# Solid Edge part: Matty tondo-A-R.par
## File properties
Title: Matty tondo/A/R
Author: DESYS
Template: Normal.par
Last saved by: s.pallini
Revision: 16
Application: Solid Edge
Tipo di contenuto documento: 0
Precisione: 0,990
Document Number: 8055/A/R
Revision: 0
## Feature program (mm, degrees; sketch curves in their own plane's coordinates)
sketch for "unnamed RevolvedProtrusion 1" plane through (0, 0, 0) normal (0, -1, 0) x-axis (1, 0, 0)
  line (-103.413, -287.9981) -> (-129.488, -287.9981)
  arc centre (-129.488, -279.9013) radius 8.0968 from (-136.7557, -283.4704) to (-129.488, -287.9981) ccw
  arc centre (491.5651, 25.0957) radius 700 from (-186.9381, -147.0479) to (-136.7557, -283.4704) ccw
  arc centre (-196.631, -149.5071) radius 10 from (-186.9381, -147.0479) to (-196.631, -139.5071) ccw
  line (-207.631, -139.5071) -> (-196.631, -139.5071)
  arc centre (469.5217, 37.8744) radius 700 from (-229.7181, 5.2599) to (-207.631, -139.5071) ccw
  arc centre (-224.7235, 5.4929) radius 5 from (-223.4856, 10.3372) to (-229.7181, 5.2599) ccw
  line (-223.4856, 10.3372) -> (-198.051, 3.8377)
  arc centre (-199.2889, -1.0066) radius 5 from (-194.3913, 0) to (-198.051, 3.8377) ccw
  arc centre (50.4896, 50.3322) radius 250 from (-194.3913, 0) to (-25, -187.9981) ccw
  line (0, -187.9981) -> (-25, -187.9981)
  line (-30, -227.9981) -> (0, -227.9981)
  arc centre (-30, -222.9981) radius 5 from (-35, -222.9981) to (-30, -227.9981) ccw
  line (-35, -211.5908) -> (-35, -222.9981)
  arc centre (-40, -211.5908) radius 5 from (-35, -211.5908) to (-38.2474, -206.908) ccw
  arc centre (-20.7216, -160.0802) radius 50 from (-55.0901, -196.3956) to (-38.2474, -206.908) ccw
  arc centre (-58.5269, -200.0271) radius 5 from (-55.0901, -196.3956) to (-63.1521, -198.1276) ccw
  line (-98.7879, -284.8976) -> (-63.1521, -198.1276)
  arc centre (-103.413, -282.9981) radius 5 from (-103.413, -287.9981) to (-98.7879, -284.8976) ccw
  dimension (linear) = 223.4856
revolve "unnamed RevolvedProtrusion 1" add full turn 360 deg about sketch line (0, -187.9981) -> (0, -227.9981)
sketch for "unnamed RevolvedCutout 1" plane through (0, 0, 0) normal (1, 0, 0) x-axis (0, 1, 0)
  line (-227.9568, -21.4867) -> (-200.6198, -21.4867)
  arc centre (93.1464, 39.3526) radius 300 from (-200.6198, -21.4867) to (-69.2229, -212.9095) ccw
revolve "unnamed RevolvedCutout 1" cut finite
fillet "Rotondo_1" radius 5
sketch for "Foro_1" plane through (0, 0, -187.9981) normal (0, 0, 1) x-axis (0, -1, 0)
  hole centre (0, 0) bore radius 25
hole "Foro_1" diameter 50 through
fillet "Rotondo_4" radius 10
fillet "Rotondo_5" radius 5
sketch for "Foro_3" plane through (0, 9.4953, -287.9981) normal (0, 0, -1) x-axis (-0.34202, 0.939693, 0)
  hole centre (31.4357, -114.1313) bore radius 7.5
hole "Foro_3" diameter 15 finite
sketch for "unnamed Hole 1" plane through (0, 9.4953, -287.9981) normal (0, 0, -1) x-axis (-0.34202, 0.939693, 0)
  hole centre (-49.281, 107.6361) bore radius 7.5
hole "unnamed Hole 1" finite
sketch for "unnamed Hole 2" plane through (0, 9.4953, -287.9981) normal (0, 0, -1) x-axis (-0.34202, 0.939693, 0)
  hole centre (101.9611, 37.1108) bore radius 7.5
hole "unnamed Hole 2" finite
fillet "Rotondo_7" radius 5
sketch for "unnamed Protrusion 1" plane through (0, 0, 0) normal (0, 0, 1) x-axis (1, 0, 0)
extrude "unnamed Protrusion 1" add through along -normal
sketch for "Foro_7" plane through (0, 0, 0) normal (0, -1, 0) x-axis (1, 0, 0)
hole "Foro_7" diameter 20 finite
sketch for "ScavoEstrusione_2" plane through (0, 0, 0) normal (1, 0, 0) x-axis (0, 1, 0)
extrude "ScavoEstrusione_2" cut finite 133 symmetric
draft "Spoglia_2"  Angles1 = 6.2 deg
draft "Spoglia_3"  Angles1 = 6.2 deg
fillet "Rotondo_8" radius 10
sketch for "ExtrudedProtrusion_2" plane through (0, 0, 0) normal (1, 0, 0) x-axis (0, 1, 0)
  line (-26.903, -223.5492) -> (-75.9297, -220.2121)
  line (-26.903, -198.1276) -> (-26.903, -223.5492)
  line (-50.898, -188.8164) -> (-26.903, -198.1276)
  line (-101.6779, -155.4366) -> (-50.898, -188.8164)
  line (-113.3964, -131.6446) -> (-101.6779, -155.4366)
  line (-113.3964, -12.3296) -> (-113.3964, -131.6446)
  line (-145.3557, -12.3296) -> (-113.3964, -12.3296)
  line (-145.3557, -12.3296) -> (-145.3557, -125.3143)
  arc centre (-73.461, -125.3143) radius 71.8947 from (-125.5893, -174.8269) to (-145.3557, -125.3143) cw
  line (-125.5893, -174.8269) -> (-85.5645, -216.9662)
  arc centre (-74.5715, -200.2583) radius 20 from (-85.5645, -216.9662) to (-75.9297, -220.2121) ccw
extrude "ExtrudedProtrusion_2" add finite 30 symmetric
fillet "Rotondo_9" radius 10
fillet "Rotondo_10" radius 5
fillet "Rotondo_11" radius 5
fillet "Rotondo_12" radius 5
sketch for "Foro_8" plane through (0, -149.5574, 0) normal (0, 0, 1) x-axis (1, 0, 0)
hole "Foro_8" diameter 35 through
fillet "Rotondo_13" radius 5
fillet "Rotondo_14" radius 10
fillet "Rotondo_15" radius 20
fillet "Rotondo_16" radius 5
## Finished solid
Body 1: solid body, 136 faces, 301 edges, 166 vertices.
  Faces by surface: blend 50, cylinder 34, torus 30, plane 16, sphere 4, cone 2
  Edges by curve: circle 130, intersection 102, line 57, ellipse 12
Bounding box of the edges (mm; curved faces can reach further): 459.436 x 459.436 x 298.335, from (-229.7181, -229.7181, -287.9981) to (229.7181, 229.7181, 10.3372).
Cylindrical faces by radius (mm): R5 x17, R10 x6, R17.5 x1, R20 x1, R25 x1, R35 x1, R56.278 x2, R60.9772 x2, R71.8947 x1, R251.0525 x2
Conical faces (half-angle, radius in mm at the cone's reference point): 22.3276 deg R63.1521 x1, 75.6654 deg R223.4856 x1
Toroidal faces (ring radius, tube radius in mm): R-491.5651 r700 x1, R-469.5217 r700 x1, R-50.4896 r250 x1, R10 r5 x2, R15 r5 x2, R20.7216 r50 x1, R22.5 r5 x1, R30 r5 x1, R35 r10 x1, R40 r5 x1, R51.278 r5 x2, R58.5269 r5 x1, R65.9772 r5 x2, R66.8947 r5 x2, R103.413 r5 x1, R129.488 r8.0968 x1, R185.7346 r20 x2, R196.631 r10 x1, R199.2889 r5 x1, R203.761 r5 x1, R218.7356 r10 x1, R224.7235 r5 x1, R256.0525 r5 x2
Spherical faces by radius (mm): R5 x4
Planar faces by outward normal: +x 1, +y 2, +z 1, -x 1, -y 3, -z 4, oblique 4
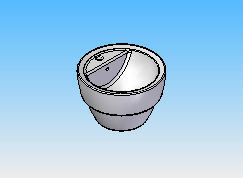
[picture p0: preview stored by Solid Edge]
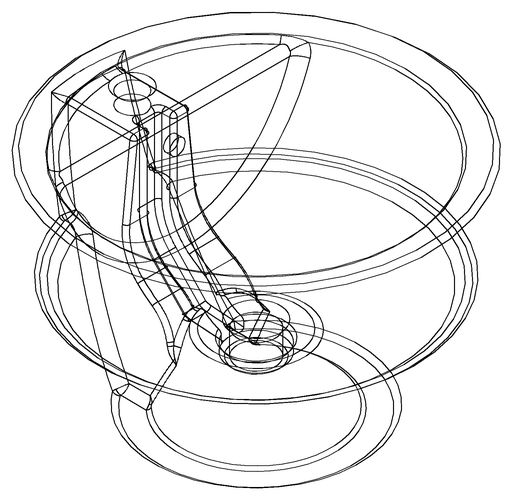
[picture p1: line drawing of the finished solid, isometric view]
